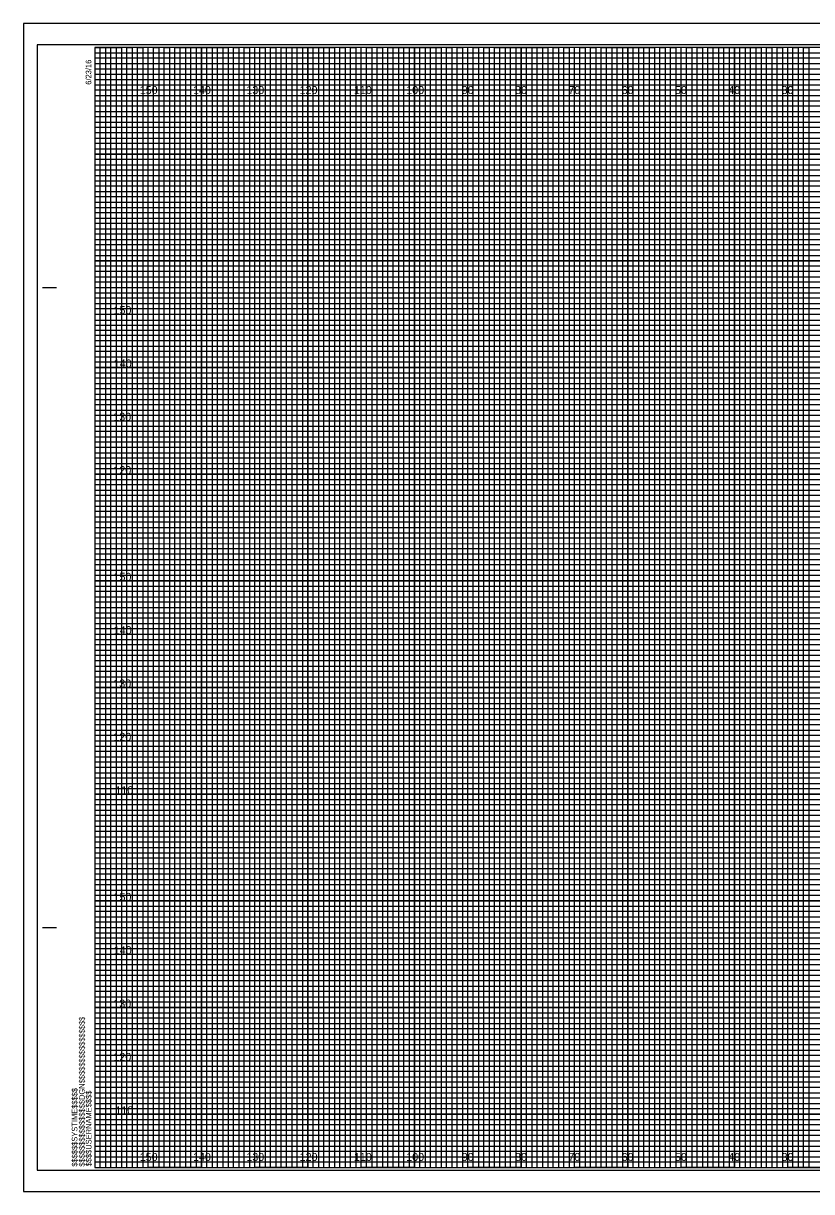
# Model space of a CAD drawing. Extents: x -13 to 323, y -5 to 1974.
# Drawn here: x -13.4 to 134.5, y 655.5 to 874.5 of the extents above; entities that cross this region are included whole.
import ezdxf

# ---------------------------------------------------------------- set-up
doc = ezdxf.new("R2010")
doc.units = 0
for name, color, linetype in [('Exist Cross Section Cell', 7, 'Continuous'), ('Exist XS Center Line Elevation Label', 7, 'Continuous'), ('Exist XS Ground Line', 7, 'Continuous'), ('Prop CMT Pvmt Course 1', 7, 'Continuous'), ('Prop CMT Pvmt Course 3', 7, 'Continuous'), ('Prop CMT Pvmt Surface', 7, 'Continuous'), ('Prop CMT Pvmt Surface Shoulder', 7, 'Continuous'), ('Prop CMT Shld Paved Course 1', 7, 'Continuous'), ('Prop CMT Shld Paved Course 2', 7, 'Continuous'), ('Prop CMT Shld Paved Course 3', 7, 'Continuous'), ('Prop CMT Subgrade Earthwork', 7, 'Continuous')]:
    doc.layers.add(name, color=color, linetype=linetype)

msp = doc.modelspace()

# ---------------------------------------------------------------- linework, layer by layer
at = {"layer": 'Exist XS Center Line Elevation Label'}
for points in [[(0, 870), (5, 870), (5, 660), (15, 660), (15, 870), (25, 870), (25, 660), (35, 660), (35, 870), (45, 870), (45, 660), (55, 660), (55, 870), (65, 870), (65, 660), (75, 660), (75, 870), (85, 870), (85, 660), (95, 660), (95, 870), (105, 870), (105, 660), (115, 660), (115, 870), (125, 870), (125, 660), (135, 660)], [(0, 865), (275, 865)], [(0, 845), (320, 845), (320, 855), (0, 855)], [(0, 825), (320, 825), (320, 835), (0, 835)], [(0, 805), (320, 805), (320, 815), (0, 815)], [(0, 785), (320, 785), (320, 795), (0, 795)], [(0, 765), (320, 765), (320, 775), (0, 775)], [(0, 745), (320, 745), (320, 755), (0, 755)], [(0, 725), (320, 725), (320, 735), (0, 735)], [(0, 705), (320, 705), (320, 715), (0, 715)], [(0, 685), (320, 685), (320, 695), (0, 695)], [(0, 665), (320, 665), (320, 675), (0, 675)]]:
    msp.add_lwpolyline(points, dxfattribs=at)
at = {"layer": 'Exist XS Ground Line'}
for p, q in [((10, 870), (0, 870)), ((10, 660), (10, 870)), ((30, 870), (20, 870)), ((20, 870), (20, 660)), ((30, 660), (30, 870)), ((50, 870), (40, 870)), ((40, 870), (40, 660)), ((50, 660), (50, 870)), ((70, 870), (60, 870)), ((60, 870), (60, 660)), ((70, 660), (70, 870)), ((90, 870), (80, 870)), ((80, 870), (80, 660)), ((90, 660), (90, 870)), ((110, 870), (100, 870)), ((100, 870), (100, 660)), ((110, 660), (110, 870)), ((130, 870), (120, 870)), ((120, 870), (120, 660)), ((130, 660), (130, 870)), ((20, 660), (10, 660)), ((40, 660), (30, 660)), ((60, 660), (50, 660)), ((80, 660), (70, 660)), ((100, 660), (90, 660)), ((120, 660), (110, 660)), ((140, 660), (130, 660))]:
    msp.add_line(p, q, dxfattribs=at)
for points in [[(0, 860), (320, 860), (320, 850), (0, 850)], [(0, 840), (320, 840), (320, 830), (0, 830)], [(0, 820), (320, 820), (320, 810), (0, 810)], [(0, 800), (320, 800), (320, 790), (0, 790)], [(0, 780), (320, 780), (320, 770), (0, 770)], [(0, 760), (320, 760), (320, 750), (0, 750)], [(0, 740), (320, 740), (320, 730), (0, 730)], [(0, 720), (320, 720), (320, 710), (0, 710)], [(0, 700), (320, 700), (320, 690), (0, 690)], [(0, 680), (320, 680), (320, 670), (0, 670)]]:
    msp.add_lwpolyline(points, dxfattribs=at)
at = {"layer": 'Prop CMT Pvmt Course 3'}
msp.add_lwpolyline([(-13.4, 655.5), (323.3, 655.5), (323.3, 874.5), (-13.4, 874.5)], close=True, dxfattribs=at)
at = {"layer": 'Prop CMT Pvmt Surface'}
for p, q in [((10, 660), (10, 870)), ((20, 660), (20, 870)), ((30, 660), (30, 870)), ((40, 660), (40, 870)), ((50, 660), (50, 870)), ((60, 660), (60, 870)), ((70, 660), (70, 870)), ((80, 660), (80, 870)), ((90, 660), (90, 870)), ((100, 660), (100, 870)), ((110, 660), (110, 870)), ((120, 660), (120, 870)), ((130, 660), (130, 870)), ((0, 860), (320, 860)), ((0, 850), (320, 850)), ((0, 840), (320, 840)), ((0, 830), (320, 830)), ((0, 820), (320, 820)), ((0, 810), (320, 810)), ((0, 800), (320, 800)), ((0, 790), (320, 790)), ((0, 780), (320, 780)), ((0, 770), (320, 770)), ((0, 760), (320, 760)), ((0, 750), (320, 750)), ((0, 740), (320, 740)), ((0, 730), (320, 730)), ((0, 720), (320, 720)), ((0, 710), (320, 710)), ((0, 700), (320, 700)), ((0, 690), (320, 690)), ((0, 680), (320, 680)), ((0, 670), (320, 670))]:
    msp.add_line(p, q, dxfattribs=at)
at = {"layer": 'Prop CMT Pvmt Surface Shoulder'}
for p, q in [((323.3, 874.5), (-13.4, 874.5)), ((-13.4, 874.5), (-13.4, 655.5)), ((-13.4, 655.5), (323.3, 655.5))]:
    msp.add_line(p, q, dxfattribs=at)
at = {"layer": 'Prop CMT Shld Paved Course 1'}
for p, q in [((0, 869), (260, 869)), ((260, 867.98), (0, 867.98)), ((0, 867.98), (0, 867)), ((0, 867), (260, 867)), ((260, 865.89), (0, 865.89)), ((0, 865.89), (0, 864)), ((0, 864), (320, 864))]:
    msp.add_line(p, q, dxfattribs=at)
for points in [[(0, 863), (270, 863), (320, 863), (320, 862), (0, 862)], [(0, 861), (320, 861), (320, 859), (0, 859)], [(0, 858), (320, 858), (320, 857), (0, 856.98)], [(0, 856), (320, 856), (320, 854), (0, 854)], [(0, 853), (320, 853), (320, 852), (0, 852)], [(0, 851), (320, 851), (320, 849), (0, 849)], [(0, 848), (320, 848), (320, 847), (0, 847)], [(0, 846), (320, 846), (320, 844), (0, 844)], [(0, 843), (320, 843), (320, 842), (0, 842)], [(0, 841), (320, 841), (320, 839), (0, 839)], [(0, 838), (320, 838), (320, 837), (0, 837)], [(0, 836), (320, 836), (320, 833.95), (320, 833), (320, 832), (0, 832)], [(0, 834), (320, 834), (320, 833), (0, 833)], [(0, 831), (320, 831), (320, 829), (0, 829.03)], [(0, 829.03), (320, 829), (320, 828), (0, 828)], [(0, 827), (320, 827), (320, 826), (0, 826)], [(0, 824), (320, 824), (320, 823), (0, 823)], [(0, 822), (320, 822), (320, 821), (0, 821)], [(-0.07, 818.89), (320, 818.89), (320, 817.88), (-0.07, 817.88)], [(0, 817), (320, 817), (320, 816), (0, 816)], [(0, 814), (320, 814), (320, 813), (0, 813)], [(0, 812), (320, 812), (320, 811), (0, 811)], [(0, 809), (320, 809), (320, 808), (0, 808)], [(0, 807), (320, 807), (320, 806), (0, 806)], [(0, 804), (320, 804), (320, 803), (0, 803)], [(0, 802), (320, 802), (320, 801), (0, 801)], [(0, 799), (320, 799), (319.99, 797.98), (0, 798)], [(0, 797), (320, 797), (320, 796), (0, 796)], [(0, 794), (320, 794), (320, 793), (0, 793)], [(0, 792), (320, 792), (320, 791), (0, 791)], [(0, 789), (320, 789), (320, 788), (0, 788)], [(0, 787), (320, 787), (320, 786), (0, 786)], [(0, 784), (320, 784), (320, 783), (0, 783)], [(0, 782), (320, 782), (320, 781), (0, 781)], [(0, 779), (320, 779), (320, 778), (0, 778)], [(0, 776.99), (320.07, 776.91), (320, 776), (0, 776)], [(0, 774), (320, 774), (320, 773), (0, 773)], [(0, 772), (320, 772), (320, 771), (0, 771)], [(0, 769), (320, 769), (320, 768), (0, 768)], [(0, 767), (320, 767), (320, 766), (0, 766)], [(0, 764), (320, 764), (320, 763), (0, 763)], [(0, 762), (320, 762), (320, 761), (0, 761)], [(0, 759), (320, 759), (320, 758), (0, 758)], [(0, 757), (320, 757), (320, 756), (0, 756)], [(0, 754), (320, 754), (320, 753), (0, 753)], [(0, 752), (320, 752), (320, 751), (0, 751)], [(0, 749), (320, 749), (320, 748), (0, 748)], [(0, 747), (320, 747), (320, 746), (0, 746)], [(0, 744), (320, 744), (320, 743), (0, 743)], [(0, 742), (320, 742), (320, 741), (0, 741)], [(0, 739), (320, 739), (319.99, 737.98), (0, 738)], [(0, 737), (320, 737), (320, 736), (0, 736)], [(0, 734), (320, 734), (320, 733), (0, 733)], [(0, 732), (320, 732), (320, 731), (0, 731)], [(0, 729), (320, 729), (320, 728), (0, 728)], [(0, 727), (320, 727), (320, 726), (0, 726)], [(0, 724), (320, 724), (320, 723), (0, 723)], [(0, 722), (320, 722), (320, 721), (0, 721)], [(0, 719), (320, 719), (320, 718), (0, 718)], [(0, 716.99), (320.07, 716.91), (320, 716), (0, 716)], [(0, 714), (320, 714), (320, 713), (0, 713)], [(0, 712), (320, 712), (320, 711), (0, 711)], [(0, 709), (320, 709), (320, 708), (0, 708)], [(0, 707), (320, 707), (320, 706), (0, 706)], [(0, 704), (320, 704), (320, 703), (0, 703)], [(0, 702), (320, 702), (320, 701), (0, 701)], [(0, 699), (320, 699), (320, 698), (0, 698)], [(0, 697), (320, 697), (320, 696), (0, 696)], [(0, 694), (320, 694), (320, 693), (0, 693)], [(0, 692), (320, 692), (320, 691), (0, 691)], [(0, 689), (320, 689), (320, 688), (0, 688)], [(0, 687), (320, 687), (320, 686), (0, 686)], [(0, 684), (320, 684), (320, 683), (0, 683)], [(0, 682), (320, 682), (320, 681), (0, 681)], [(0, 679), (320, 679), (320, 678), (0, 678)], [(0, 677), (320, 677), (320, 676), (0, 676)], [(0, 674), (320, 674), (320, 673), (0, 673)], [(0, 672), (320, 672), (320, 671), (0, 671)], [(0, 669), (320, 669), (320, 668), (0, 668)], [(0, 667), (320, 667), (320, 666), (0, 666)], [(0, 664), (320, 664), (320, 663), (0, 663)], [(0, 662), (320, 662), (320, 661), (0, 661)]]:
    msp.add_lwpolyline(points, dxfattribs=at)
at = {"layer": 'Prop CMT Shld Paved Course 2'}
for p, q in [((-9.8, 825), (-7.3, 825)), ((-9.7, 825), (-7.2, 825)), ((-9.8, 705), (-7.3, 705)), ((-9.7, 705), (-7.2, 705)), ((0, 660), (0, 660)), ((0, 660), (0, 660)), ((0, 660), (0, 660)), ((0, 660), (0, 660)), ((0, 660), (0, 660)), ((0, 660), (0, 660)), ((0, 660), (0, 660))]:
    msp.add_line(p, q, dxfattribs=at)
msp.add_lwpolyline([(320, 870), (0, 870), (0, 660), (320, 660)], close=True, dxfattribs=at)
at = {"layer": 'Prop CMT Shld Paved Course 3'}
for points in [[(0, 660), (1, 660), (1, 870), (2, 870), (2, 660)], [(2, 660), (3, 660), (3, 870), (4, 870), (4, 660)], [(5, 660), (6, 660), (6, 870), (7, 870), (7, 660)], [(7, 660), (8, 660), (8, 870), (9, 870), (9, 660)], [(10, 660), (11, 660), (11, 870), (12, 870), (12, 660)], [(12, 660), (13, 660), (13, 870), (14, 870), (14, 660)], [(15, 660), (16, 660), (16, 870), (17, 870), (17, 660)], [(17, 660), (18, 660), (18, 870), (19, 870), (19, 660)], [(20, 660), (21, 660), (21, 870), (22, 870), (22, 660)], [(22, 660), (23, 660), (23, 870), (24, 870), (24, 660)], [(25, 660), (26, 660), (26, 870), (27, 870), (27, 660)], [(27, 660), (28, 660), (28, 870), (29, 870), (29, 660)], [(30, 660), (31, 660), (31, 870), (32, 870), (32, 660)], [(32, 660), (33, 660), (33, 870), (34, 870), (34, 660)], [(35, 660), (36, 660), (36, 870), (37, 870), (37, 660)], [(37, 660), (38, 660), (38, 870), (39, 870), (39, 660)], [(40, 660), (41, 660), (41, 870), (42, 870), (42, 660)], [(42, 660), (43, 660), (43, 870), (44, 870), (44, 660)], [(45, 660), (46, 660), (46, 870), (47, 870), (47, 660)], [(47, 660), (48, 660), (48, 870), (49, 870), (49, 660)], [(50, 660), (51, 660), (51, 870), (52, 870), (52, 660)], [(52, 660), (53, 660), (53, 870), (54, 870), (54, 660)], [(55, 660), (56, 660), (56, 870), (57, 870), (57, 660)], [(57, 660), (58, 660), (58, 870), (59, 870), (59, 660)], [(60, 660), (61, 660), (61, 870), (62, 870), (62, 660)], [(62, 660), (63, 660), (63, 870), (64, 870), (64, 660)], [(65, 660), (66, 660), (66, 870), (67, 870), (67, 660)], [(67, 660), (68, 660), (68, 870), (69, 870), (69, 660)], [(70, 660), (71, 660), (71, 870), (72, 870), (72, 660)], [(72, 660), (73, 660), (73, 870), (74, 870), (74, 660)], [(75, 660), (76, 660), (76, 870), (77, 870), (77, 660)], [(77, 660), (78, 660), (78, 870), (79, 870), (79, 660)], [(80, 660), (81, 660), (81, 870), (82, 870), (82, 660)], [(82, 660), (83, 660), (83, 870), (84, 870), (84, 660)], [(85, 660), (86, 660), (86, 870), (87, 870), (87, 660)], [(87, 660), (88, 660), (88, 870), (89, 870), (89, 660)], [(90, 660), (91, 660), (91, 870), (92, 870), (92, 660)], [(92, 660), (93, 660), (93, 870), (94, 870), (94, 660)], [(95, 660), (96, 660), (96, 870), (97, 870), (97, 660)], [(97, 660), (98, 660), (98, 870), (99, 870), (99, 660)], [(100, 660), (101, 660), (101, 870), (102, 870), (102, 660)], [(102, 660), (103, 660), (103, 870), (104, 870), (104, 660)], [(105, 660), (106, 660), (106, 870), (107, 870), (107, 660)], [(107, 660), (108, 660), (108, 870), (109, 870), (109, 660)], [(110, 660), (111, 660), (111, 870), (112, 870), (112, 660)], [(112, 660), (113, 660), (113, 870), (114, 870), (114, 660)], [(115, 660), (116, 660), (116, 870), (117, 870), (117, 660)], [(117, 660), (118, 660), (118, 870), (119, 870), (119, 660)], [(120, 660), (121, 660), (121, 870), (122, 870), (122, 660)], [(122, 660), (123, 660), (123, 870), (124, 870), (124, 660)], [(125, 660), (126, 660), (126, 870), (127, 870), (127, 660)], [(127, 660), (128, 660), (128, 870), (129, 870), (129, 660)], [(130, 660), (131, 660), (131, 870), (132, 870), (132, 660)], [(132, 660), (133, 660), (133, 870), (134, 870), (134, 660)]]:
    msp.add_lwpolyline(points, dxfattribs=at)
at = {"layer": 'Prop CMT Subgrade Earthwork'}
msp.add_lwpolyline([(-10.8, 659.5), (322.4, 659.5), (322.4, 870.5), (-10.8, 870.5)], close=True, dxfattribs=at)

# ---------------------------------------------------------------- texts
at = {"layer": 'Exist Cross Section Cell'}
for s, p in [('150', (8.44, 861.25)), ('140', (18.44, 861.25)), ('130', (28.44, 861.25)), ('120', (38.44, 861.25)), ('110', (48.62, 861.25)), ('100', (58.44, 861.25)), ('90', (68.86, 861.25)), ('80', (78.86, 861.25)), ('70', (88.86, 861.25)), ('60', (98.86, 861.25)), ('50', (108.86, 861.25)), ('40', (118.86, 861.25)), ('30', (128.86, 861.25)), ('150', (8.44, 661.25)), ('140', (18.44, 661.25)), ('130', (28.44, 661.25)), ('120', (38.44, 661.25)), ('110', (48.62, 661.25)), ('100', (58.44, 661.25)), ('90', (68.86, 661.25)), ('80', (78.86, 661.25)), ('70', (88.86, 661.25)), ('60', (98.86, 661.25)), ('50', (108.86, 661.25)), ('40', (118.86, 661.25)), ('30', (128.86, 661.25))]:
    msp.add_text(s, height=1.5, dxfattribs=at).set_placement(p)
at = {"layer": 'Prop CMT Pvmt Course 1'}
for s, p in [('150', (3.52, 820)), ('140', (3.57, 810)), ('130', (3.49, 800)), ('120', (3.5, 790)), ('150', (3.52, 770)), ('140', (3.57, 760)), ('130', (3.49, 750)), ('120', (3.5, 740)), ('110', (3.88, 730)), ('150', (3.52, 710)), ('140', (3.57, 700)), ('130', (3.49, 690)), ('120', (3.5, 680)), ('110', (3.88, 670))]:
    msp.add_text(s, height=1.5, dxfattribs=at).set_placement(p)
at = {"layer": 'Prop CMT Shld Paved Course 2'}
for s, p in [('6/23/16', (-0.65, 863)), ('$$$$$$$$$$$$$$$$DGN$$$$$$$$$$$$$$$$', (-1.88, 660.18)), ('$$$$$$SYSTIME$$$$$', (-3.26, 660.18)), ('$$$$USERNAME$$$$', (-0.62, 660.23))]:
    msp.add_text(s, height=1.05, rotation=90, dxfattribs=at).set_placement(p)

doc.saveas('drawing.dxf')
